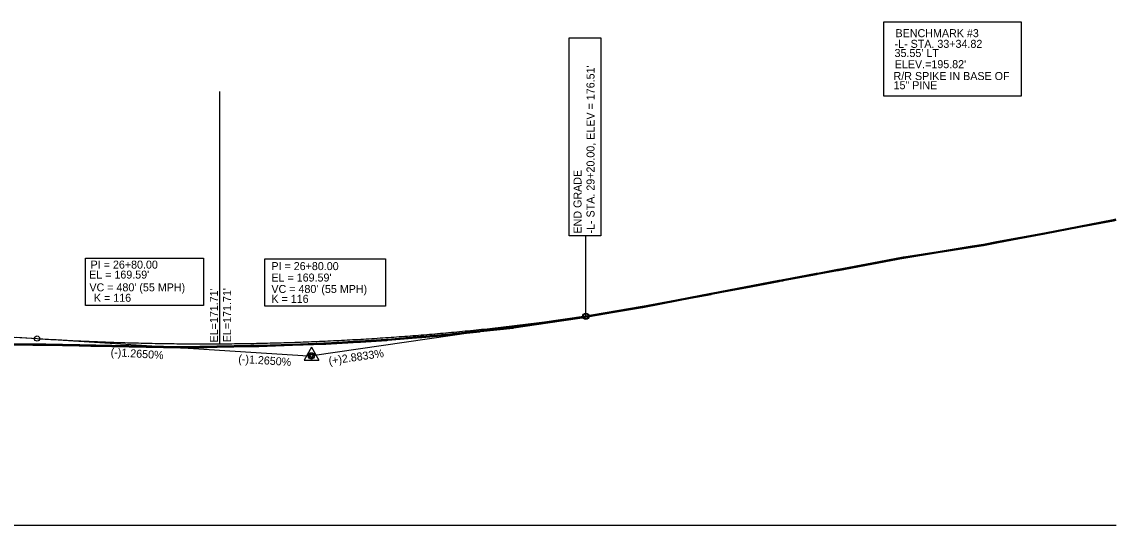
# Model space of a CAD drawing. Extents: x 2321227 to 2323611, y 920570 to 921870.
# Drawn here: x 2322654 to 2323611, y 920570 to 921010 of the extents above; entities that cross this region are included whole.
import ezdxf

# ---------------------------------------------------------------- set-up
doc = ezdxf.new("R2010")
doc.units = 0
for name, color, linetype in [('Exist Profile Cell', 7, 'Continuous'), ('Exist Vertical Profile Ground Line', 7, 'Continuous'), ('Prop CMT PFL Best Fit', 7, 'Continuous'), ('Prop Grid Mask', 7, 'Continuous'), ('Prop PFL Text', 7, 'Continuous'), ('Prop PFL VPI Symbol CELL', 7, 'Continuous'), ('Prop Vertical Profile Curve Label', 7, 'Continuous'), ('Prop Vertical Profile Grade', 7, 'Continuous'), ('Prop Vertical Profile Grade Label', 7, 'Continuous'), ('Prop VPI Label', 7, 'Continuous'), ('Scratch_Level_1', 7, 'Continuous'), ('Scratch_Level_2', 7, 'Continuous')]:
    doc.layers.add(name, color=color, linetype=linetype)

# ---------------------------------------------------------------- blocks, each defined once
blk = doc.blocks.new('Profile VPI Symbol')
at = {"layer": 'Prop PFL VPI Symbol CELL'}
for p, q in [((-0.001, 0.147), (-0.13, -0.077)), ((-0.001, 0.147), (0.129, -0.077)), ((-0.13, -0.077), (0.129, -0.077))]:
    blk.add_line(p, q, dxfattribs=at)
for radius in [0.035, 0.024]:
    blk.add_circle((-0.001, -0.003), radius, dxfattribs=at)

msp = doc.modelspace()

# ---------------------------------------------------------------- linework, layer by layer
at = {"layer": 'Exist Profile Cell'}
msp.add_line((2321226.97, 920570.07), (2323610.74, 920570.07), dxfattribs=at)
at = {"layer": 'Exist Vertical Profile Ground Line'}
for p, q in [((2323578.34, 920830.42), (2323608.31, 920836.18)), ((2323608.31, 920836.18), (2323610.74, 920836.65)), ((2323524.87, 920820.26), (2323548.37, 920824.66)), ((2323548.37, 920824.66), (2323578.34, 920830.42)), ((2323455.15, 920808.28), (2323485.11, 920813.08)), ((2323485.11, 920813.08), (2323494.87, 920814.64)), ((2323494.87, 920814.64), (2323506.43, 920816.81)), ((2323506.43, 920816.81), (2323524.87, 920820.26)), ((2323397.18, 920798.25), (2323424.83, 920803.43)), ((2323424.83, 920803.43), (2323425.17, 920803.49)), ((2323425.17, 920803.49), (2323455.15, 920808.28)), ((2323367.2, 920792.65), (2323367.95, 920792.79)), ((2323367.95, 920792.79), (2323397.18, 920798.25)), ((2323315.95, 920783.05), (2323316.95, 920783.22)), ((2323316.95, 920783.22), (2323319.5, 920783.72)), ((2323319.5, 920783.72), (2323319.84, 920783.79)), ((2323319.84, 920783.79), (2323348.76, 920789.19)), ((2323348.76, 920789.19), (2323349.67, 920789.38)), ((2323349.67, 920789.38), (2323367.2, 920792.65)), ((2323264.49, 920773.32), (2323286.89, 920777.56)), ((2323286.89, 920777.56), (2323315.95, 920783.05)), ((2323196.75, 920760.41), (2323226.51, 920766.09)), ((2323226.51, 920766.09), (2323238.44, 920768.37)), ((2323238.44, 920768.37), (2323256.44, 920771.79)), ((2323256.44, 920771.79), (2323256.85, 920771.86)), ((2323256.85, 920771.86), (2323264.49, 920773.32)), ((2323141.79, 920751.11), (2323171.89, 920756.2)), ((2323171.89, 920756.2), (2323196.41, 920760.35)), ((2323196.41, 920760.35), (2323196.75, 920760.41)), ((2323083.87, 920742.44), (2323113.64, 920746.89)), ((2323113.64, 920746.89), (2323141.79, 920751.11)), ((2323003.67, 920734.16), (2323024.28, 920735.9)), ((2323024.28, 920735.9), (2323025.25, 920736.01)), ((2323025.25, 920736.01), (2323054.24, 920739.18)), ((2323054.24, 920739.18), (2323054.96, 920739.27)), ((2323054.96, 920739.27), (2323083.45, 920742.38)), ((2323083.45, 920742.38), (2323083.87, 920742.44)), ((2322642.71, 920727.79), (2322663.25, 920727.52)), ((2322663.25, 920727.52), (2322671.85, 920727.41)), ((2322671.85, 920727.41), (2322672.71, 920727.38)), ((2322672.71, 920727.38), (2322673.73, 920727.37)), ((2322673.73, 920727.37), (2322674.55, 920727.36)), ((2322674.55, 920727.36), (2322703.72, 920726.84)), ((2322703.72, 920726.84), (2322704.33, 920726.83)), ((2322704.33, 920726.83), (2322714.09, 920726.65)), ((2322714.09, 920726.65), (2322732.38, 920726.32)), ((2322732.38, 920726.32), (2322762.37, 920725.74)), ((2322762.37, 920725.74), (2322764.94, 920725.69)), ((2322764.94, 920725.69), (2322777.61, 920725.44)), ((2322824.63, 920725.65), (2322854.07, 920726.19)), ((2322854.07, 920726.19), (2322854.67, 920726.2)), ((2322854.67, 920726.2), (2322860.46, 920726.31)), ((2322860.46, 920726.31), (2322861.11, 920726.33)), ((2322861.11, 920726.33), (2322890.45, 920727.31)), ((2322890.45, 920727.31), (2322917.98, 920728.23)), ((2322917.98, 920728.23), (2322918.88, 920728.26)), ((2322918.88, 920728.26), (2322919.55, 920728.29)), ((2322919.55, 920728.29), (2322948.57, 920730.08)), ((2322948.57, 920730.08), (2322949.76, 920730.13)), ((2322949.76, 920730.13), (2322972.79, 920731.55)), ((2322972.79, 920731.55), (2322973.83, 920731.64)), ((2322973.83, 920731.64), (2323002.49, 920734.06)), ((2323002.49, 920734.06), (2323003.67, 920734.16)), ((2322777.61, 920725.44), (2322792.39, 920725.15)), ((2322792.39, 920725.15), (2322794.59, 920725.1)), ((2322794.59, 920725.1), (2322815.79, 920725.49)), ((2322815.79, 920725.49), (2322824.25, 920725.64)), ((2322824.25, 920725.64), (2322824.63, 920725.65))]:
    msp.add_line(p, q, dxfattribs=at)
at = {"layer": 'Prop CMT PFL Best Fit'}
msp.add_lwpolyline([(2322726.97, 920727.15), (2322796.97, 920725.88), (2322866.97, 920727.26), (2322916.97, 920728.93), (2322976.97, 920732.64), (2323026.97, 920736.93), (2323076.97, 920742.4), (2323086.97, 920743.63), (2323126.97, 920749.62)], dxfattribs=at)
at = {"layer": 'Prop Grid Mask'}
msp.add_line((2322826.97, 920728.62), (2322826.97, 920949.31), dxfattribs=at)
for points in [[(2323407.7, 921010.03), (2323527.7, 921010.03), (2323527.7, 920945.03), (2323407.7, 920945.03)], [(2323160.14, 920823), (2323132.24, 920823), (2323132.24, 920995.95), (2323160.14, 920995.95)], [(2322709.25, 920803.4), (2322812.57, 920803.4), (2322812.57, 920762.17), (2322709.25, 920762.17)], [(2322866.33, 920802.75), (2322971.78, 920802.75), (2322971.78, 920761.51), (2322866.33, 920761.51)]]:
    msp.add_lwpolyline(points, close=True, dxfattribs=at)
at = {"layer": 'Prop Vertical Profile Curve Label'}
msp.add_line((2323146.97, 920752.52), (2323146.97, 920823), dxfattribs=at)
for centre in [(2323146.97, 920752.62), (2322666.97, 920733.2)]:
    msp.add_circle(centre, 2.25, dxfattribs=at)
at = {"layer": 'Prop Vertical Profile Grade'}
msp.add_line((2322641.97, 920734.79), (2322666.97, 920733.2), dxfattribs=at)
msp.add_spline([(2322666.97, 920733.2), (2322676.57, 920732.62), (2322686.17, 920732.07), (2322695.77, 920731.56), (2322705.37, 920731.09), (2322714.97, 920730.67), (2322724.57, 920730.28), (2322734.17, 920729.93), (2322743.77, 920729.62), (2322753.37, 920729.35), (2322762.97, 920729.12), (2322772.57, 920728.93), (2322782.17, 920728.79), (2322791.77, 920728.68), (2322801.37, 920728.61), (2322810.97, 920728.58), (2322820.57, 920728.59), (2322830.17, 920728.64), (2322839.77, 920728.73), (2322849.37, 920728.86), (2322858.97, 920729.02), (2322868.57, 920729.23), (2322878.17, 920729.48), (2322887.77, 920729.77), (2322897.37, 920730.1), (2322906.97, 920730.47), (2322916.57, 920730.88), (2322926.17, 920731.33), (2322935.77, 920731.81), (2322945.37, 920732.34), (2322954.97, 920732.91), (2322964.57, 920733.52), (2322974.17, 920734.16), (2322983.77, 920734.85), (2322993.37, 920735.58), (2323002.97, 920736.34), (2323012.57, 920737.15), (2323022.17, 920738), (2323031.77, 920738.88), (2323041.37, 920739.81), (2323050.97, 920740.78), (2323060.57, 920741.78), (2323070.17, 920742.83), (2323079.77, 920743.91), (2323089.37, 920745.04), (2323098.97, 920746.2), (2323108.57, 920747.41), (2323118.17, 920748.65), (2323127.77, 920749.94), (2323137.37, 920751.26), (2323146.97, 920752.62)], degree=3, dxfattribs=at)
at = {"layer": 'Prop VPI Label'}
for p, q in [((2323146.97, 920752.62), (2322909.69, 920718.42)), ((2322666.97, 920733.2), (2322904.23, 920718.2))]:
    msp.add_line(p, q, dxfattribs=at)
for centre in [(2323146.97, 920752.62), (2322906.97, 920718.02)]:
    msp.add_circle(centre, 2.75, dxfattribs=at)
at = {"layer": 'Scratch_Level_1'}
for points in [[(2322642.73, 920728.41), (2322671.87, 920728.03), (2322672.73, 920728.01), (2322673.74, 920727.99), (2322674.56, 920727.98), (2322703.73, 920727.46), (2322704.34, 920727.46), (2322732.39, 920726.95), (2322762.39, 920726.36), (2322777.62, 920726.07), (2322792.41, 920725.77), (2322794.59, 920725.73), (2322824.24, 920726.27), (2322824.62, 920726.28), (2322854.05, 920726.81), (2322854.66, 920726.83), (2322860.44, 920726.93), (2322861.09, 920726.96), (2322890.43, 920727.93), (2322917.95, 920728.85), (2322918.85, 920728.89), (2322919.52, 920728.92), (2322948.54, 920730.7), (2322949.73, 920730.76), (2322972.75, 920732.17), (2322973.78, 920732.26), (2323002.43, 920734.68), (2323003.61, 920734.78), (2323024.21, 920736.52), (2323025.18, 920736.63), (2323054.17, 920739.81), (2323054.9, 920739.89), (2323083.37, 920743), (2323083.78, 920743.06), (2323113.55, 920747.51), (2323141.7, 920751.73), (2323196.3, 920760.96), (2323196.63, 920761.02), (2323226.4, 920766.7), (2323238.33, 920768.98), (2323256.32, 920772.4), (2323256.74, 920772.48), (2323264.37, 920773.94), (2323315.83, 920783.66), (2323316.84, 920783.84), (2323319.37, 920784.33), (2323319.72, 920784.4), (2323348.64, 920789.81), (2323349.55, 920789.99), (2323367.08, 920793.26), (2323367.83, 920793.4), (2323397.06, 920798.87), (2323424.72, 920804.04), (2323425.06, 920804.1), (2323455.05, 920808.9), (2323485.01, 920813.7), (2323494.76, 920815.26), (2323506.32, 920817.43), (2323548.26, 920825.27), (2323608.2, 920836.8), (2323610.62, 920837.26)], [(2322642.74, 920728.89), (2322671.88, 920728.51), (2322672.74, 920728.48), (2322673.74, 920728.47), (2322674.57, 920728.46), (2322703.73, 920727.94), (2322704.34, 920727.93), (2322732.4, 920727.42), (2322762.4, 920726.84), (2322777.63, 920726.54), (2322792.42, 920726.25), (2322794.59, 920726.2), (2322824.23, 920726.74), (2322824.61, 920726.75), (2322854.04, 920727.29), (2322854.65, 920727.3), (2322860.42, 920727.41), (2322861.07, 920727.43), (2322890.42, 920728.41), (2322917.94, 920729.33), (2322918.83, 920729.36), (2322919.49, 920729.39), (2322948.51, 920731.18), (2322949.7, 920731.23), (2322972.71, 920732.65), (2322973.74, 920732.74), (2323002.39, 920735.15), (2323003.57, 920735.26), (2323024.17, 920737), (2323025.13, 920737.11), (2323054.12, 920740.28), (2323054.84, 920740.36), (2323083.32, 920743.47), (2323083.71, 920743.53), (2323113.48, 920747.98), (2323141.62, 920752.2), (2323196.22, 920761.43), (2323196.55, 920761.49), (2323226.31, 920767.17), (2323238.24, 920769.45), (2323256.24, 920772.87), (2323256.65, 920772.95), (2323264.28, 920774.4), (2323315.75, 920784.13), (2323316.75, 920784.31), (2323319.28, 920784.8), (2323319.63, 920784.87), (2323348.55, 920790.27), (2323349.46, 920790.46), (2323367, 920793.73), (2323367.75, 920793.87), (2323396.98, 920799.33), (2323424.63, 920804.51), (2323424.98, 920804.57), (2323454.98, 920809.37), (2323484.94, 920814.17), (2323494.68, 920815.73), (2323506.23, 920817.89), (2323548.17, 920825.74), (2323608.11, 920837.26), (2323610.53, 920837.73)]]:
    msp.add_lwpolyline(points, dxfattribs=at)
at = {"layer": 'Scratch_Level_2'}
msp.add_lwpolyline([(2322649.22, 920734.33), (2322666.97, 920733.2), (2322676.97, 920732.59), (2322686.97, 920732.03), (2322696.97, 920731.5), (2322706.97, 920731.02), (2322716.97, 920730.58), (2322726.96, 920730.19)], dxfattribs=at)

# ---------------------------------------------------------------- block references
at = {"layer": 'Prop Grid Mask', "xscale": 50, "yscale": 50}
msp.add_blockref('Profile VPI Symbol', (2322907.01, 920718.16), dxfattribs=at)

# ---------------------------------------------------------------- texts
at = {"layer": 'Prop PFL Text'}
for s, p in [('BENCHMARK #3', (2323417.82, 920996.67)), ('-L- STA. 33+34.82', (2323416.98, 920987.34)), ("35.55' LT", (2323416.98, 920979.32)), ("ELEV.=195.82'", (2323417.16, 920969.55)), ('R/R SPIKE IN BASE OF', (2323416.1, 920959.19)), ('15" PINE', (2323416.1, 920951.17))]:
    msp.add_text(s, height=7, rotation=360, dxfattribs=at).set_placement(p)
at = {"layer": 'Prop Vertical Profile Curve Label'}
for s, p in [("VC = 480' (55 MPH)", (2322712.8, 920774.45)), ("VC = 480' (55 MPH)", (2322871.97, 920773.02)), ('K = 116', (2322716.75, 920765.31)), ('K = 116', (2322871.97, 920764.4))]:
    msp.add_text(s, height=7, dxfattribs=at).set_placement(p)
at = {"layer": 'Prop Vertical Profile Grade Label'}
for s, rotation, p in [('(-)1.2650%', 356.38086, (2322731.21, 920717.99)), ('(-)1.2650%', 356.38086, (2322842.83, 920712.06)), ('(+)2.8833%', 8.20362, (2322922.52, 920710.16))]:
    msp.add_text(s, height=7, rotation=rotation, dxfattribs=at).set_placement(p)
at = {"layer": 'Prop VPI Label'}
for s, p in [("-L- STA. 29+20.00, ELEV = 176.51'", (2323154.55, 920825)), ('END GRADE', (2323143.18, 920825)), ("EL=171.71'", (2322825.21, 920729.76)), ("EL=171.71'", (2322836.7, 920729.95))]:
    msp.add_text(s, height=7, rotation=90, dxfattribs=at).set_placement(p)
for s, p in [("EL = 169.59'", (2322712.54, 920785.6)), ('PI = 26+80.00', (2322713.85, 920794.31)), ('PI = 26+80.00', (2322871.97, 920793.02)), ("EL = 169.59'", (2322871.97, 920783.02))]:
    msp.add_text(s, height=7, dxfattribs=at).set_placement(p)

doc.saveas('drawing.dxf')
